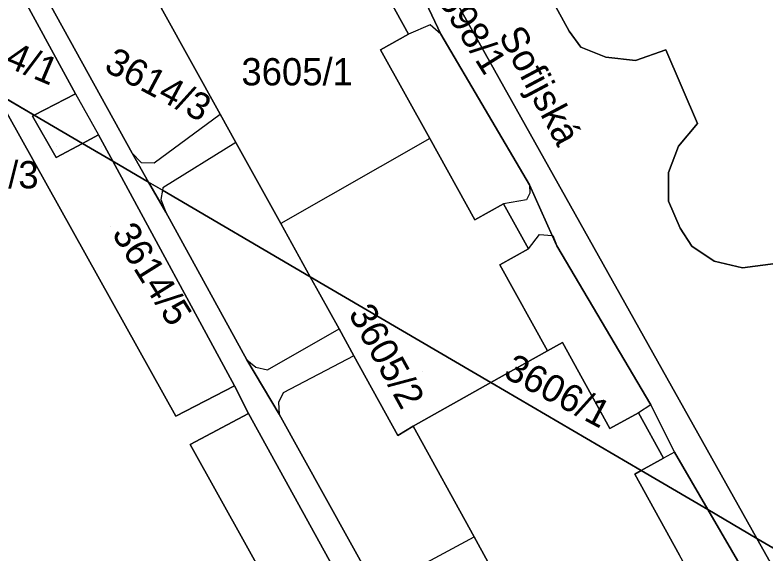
# Model space of a CAD drawing. Extents: x -262715 to -259381, y -1237238 to -1231182.
# Drawn here: x -261657.7 to -261602.6, y -1236025.5 to -1235986 of the extents above; entities that cross this region are included whole.
import ezdxf

# ---------------------------------------------------------------- set-up
doc = ezdxf.new("R2010")
doc.units = 0
for name, color, linetype in [('body_kn', 7, 'Continuous'), ('kladpar_druhypozemkov', 7, 'Continuous'), ('kladpar_hranice', 7, 'Continuous'), ('kladpar_parcelnecisla', 7, 'Continuous'), ('kladpar_plochy', 7, 'Continuous'), ('kladpar_sipky', 7, 'Continuous'), ('popisy', 7, 'Continuous'), ('zappar_hrandruhpozemk', 7, 'Continuous')]:
    doc.layers.add(name, color=color, linetype=linetype)

msp = doc.modelspace()

# ---------------------------------------------------------------- linework, layer by layer
at = {"layer": 'body_kn'}
for p, q in [((-261627.23, -1235986.66), (-261627.23, -1235986.66)), ((-261628.81, -1235987.35), (-261628.81, -1235987.35)), ((-261626.44, -1235987.35), (-261626.44, -1235987.35)), ((-261626.44, -1235987.35), (-261626.44, -1235987.35)), ((-261617.04, -1235987.14), (-261617.04, -1235987.14)), ((-261616.18, -1235988.31), (-261616.18, -1235988.31)), ((-261630.88, -1235988.5), (-261630.88, -1235988.5)), ((-261609.93, -1235988.5), (-261609.93, -1235988.5)), ((-261614.35, -1235989.05), (-261614.35, -1235989.05)), ((-261612.17, -1235989.28), (-261612.17, -1235989.28)), ((-261653.25, -1235991.72), (-261653.25, -1235991.72)), ((-261653.25, -1235991.72), (-261653.25, -1235991.72)), ((-261656.41, -1235993.37), (-261656.41, -1235993.37)), ((-261656.41, -1235993.37), (-261656.41, -1235993.37)), ((-261656.28, -1235993.3), (-261656.28, -1235993.3)), ((-261642.65, -1235993.21), (-261642.65, -1235993.21)), ((-261607.62, -1235993.9), (-261607.62, -1235993.9)), ((-261651.57, -1235994.73), (-261651.57, -1235994.73)), ((-261627.26, -1235995.01), (-261627.26, -1235995.01)), ((-261627.26, -1235995.01), (-261627.26, -1235995.01)), ((-261652.75, -1235995.36), (-261652.75, -1235995.36)), ((-261652.75, -1235995.36), (-261652.75, -1235995.36)), ((-261641.49, -1235995.3), (-261641.49, -1235995.3)), ((-261641.49, -1235995.3), (-261641.49, -1235995.3)), ((-261609.01, -1235995.56), (-261609.01, -1235995.56)), ((-261649.11, -1235996.09), (-261649.11, -1235996.09)), ((-261649.11, -1235996.09), (-261649.11, -1235996.09)), ((-261654.68, -1235996.39), (-261654.68, -1235996.39)), ((-261650.52, -1235996.67), (-261650.52, -1235996.67)), ((-261650.52, -1235996.67), (-261650.52, -1235996.67)), ((-261648.45, -1235996.76), (-261648.45, -1235996.76)), ((-261647.49, -1235996.79), (-261647.49, -1235996.79)), ((-261609.73, -1235997.49), (-261609.73, -1235997.49)), ((-261647.9, -1235998.2), (-261647.9, -1235998.2)), ((-261647.9, -1235998.2), (-261647.9, -1235998.2)), ((-261646.88, -1235998.8), (-261646.88, -1235998.8)), ((-261646.85, -1235998.61), (-261646.85, -1235998.61)), ((-261619.93, -1235998.41), (-261619.93, -1235998.41)), ((-261619.93, -1235998.41), (-261619.93, -1235998.41)), ((-261646.99, -1235999.48), (-261646.99, -1235999.48)), ((-261620.17, -1235999.49), (-261620.17, -1235999.49)), ((-261619.91, -1235999.02), (-261619.91, -1235999.02)), ((-261621.85, -1235999.8), (-261621.85, -1235999.8)), ((-261609.73, -1235999.59), (-261609.73, -1235999.59)), ((-261646.63, -1236000.41), (-261646.63, -1236000.41)), ((-261623.95, -1236000.97), (-261623.95, -1236000.97)), ((-261638.2, -1236001.24), (-261638.2, -1236001.24)), ((-261608.89, -1236001.57), (-261608.89, -1236001.57)), ((-261619.2, -1236002.04), (-261619.2, -1236002.04)), ((-261618.27, -1236002.12), (-261618.27, -1236002.12)), ((-261618.27, -1236002.12), (-261618.27, -1236002.12)), ((-261618.24, -1236002.12), (-261618.24, -1236002.12)), ((-261620.02, -1236003.09), (-261620.02, -1236003.09)), ((-261620.02, -1236003.09), (-261620.02, -1236003.09)), ((-261617.93, -1236002.88), (-261617.93, -1236002.88)), ((-261608.04, -1236002.91), (-261608.04, -1236002.91)), ((-261622.12, -1236004.26), (-261622.12, -1236004.26)), ((-261606.38, -1236003.99), (-261606.38, -1236003.99)), ((-261604.3, -1236004.48), (-261604.3, -1236004.48)), ((-261636.04, -1236005.14), (-261636.04, -1236005.14)), ((-261636.04, -1236005.14), (-261636.04, -1236005.14)), ((-261633.92, -1236008.96), (-261633.92, -1236008.96)), ((-261617.53, -1236009.97), (-261617.53, -1236009.97)), ((-261632.84, -1236010.93), (-261632.84, -1236010.93)), ((-261632.84, -1236010.93), (-261632.84, -1236010.93)), ((-261618.61, -1236010.57), (-261618.61, -1236010.57)), ((-261640.68, -1236011.22), (-261640.68, -1236011.22)), ((-261640.68, -1236011.22), (-261640.68, -1236011.22)), ((-261640.02, -1236011.77), (-261640.02, -1236011.77)), ((-261639.16, -1236011.97), (-261639.16, -1236011.97)), ((-261641.6, -1236013.13), (-261641.6, -1236013.13)), ((-261622.77, -1236012.9), (-261622.77, -1236012.9)), ((-261622.77, -1236012.9), (-261622.77, -1236012.9)), ((-261638.01, -1236013.65), (-261638.01, -1236013.65)), ((-261638.35, -1236014.35), (-261638.35, -1236014.35)), ((-261611.03, -1236014.53), (-261611.03, -1236014.53)), ((-261611.03, -1236014.53), (-261611.03, -1236014.53)), ((-261645.89, -1236015.37), (-261645.89, -1236015.37)), ((-261640.57, -1236015.16), (-261640.57, -1236015.16)), ((-261640.57, -1236015.16), (-261640.57, -1236015.16)), ((-261638.32, -1236015.22), (-261638.32, -1236015.22)), ((-261611.94, -1236015.11), (-261611.94, -1236015.11)), ((-261628.48, -1236016.1), (-261628.48, -1236016.1)), ((-261614.05, -1236016.27), (-261614.05, -1236016.27)), ((-261629.6, -1236016.78), (-261629.6, -1236016.78)), ((-261644.84, -1236017.45), (-261644.84, -1236017.45)), ((-261609.31, -1236017.99), (-261609.31, -1236017.99)), ((-261609.31, -1236017.99), (-261609.31, -1236017.99)), ((-261610.1, -1236018.45), (-261610.1, -1236018.45)), ((-261612.21, -1236019.61), (-261612.21, -1236019.61)), ((-261612.21, -1236019.61), (-261612.21, -1236019.61)), ((-261611.74, -1236019.35), (-261611.74, -1236019.35)), ((-261606.85, -1236022.21), (-261606.85, -1236022.21)), ((-261606.85, -1236022.21), (-261606.85, -1236022.21)), ((-261624, -1236024.2), (-261624, -1236024.2)), ((-261603.25, -1236024.32), (-261603.25, -1236024.32)), ((-261603.25, -1236024.32), (-261603.25, -1236024.32))]:
    msp.add_line(p, q, dxfattribs=at)
at = {"layer": 'kladpar_druhypozemkov'}
for p, q in [((-261637.15, -1235989.27), (-261637.15, -1235989.27)), ((-261654.2, -1235996.18), (-261654.2, -1235996.18)), ((-261651.69, -1235996.09), (-261651.69, -1235996.09)), ((-261650.66, -1236001.48), (-261650.66, -1236001.48)), ((-261627.8, -1236012.12), (-261627.8, -1236012.12)), ((-261617.86, -1236012.24), (-261617.86, -1236012.24))]:
    msp.add_line(p, q, dxfattribs=at)
at = {"layer": 'kladpar_hranice'}
for p, q in [((-261659.15, -1235991.62), (-261656.28, -1235993.3)), ((-261656.28, -1235993.3), (-261659.15, -1235991.62)), ((-261656.41, -1235993.37), (-261656.28, -1235993.3)), ((-261656.28, -1235993.3), (-261652.75, -1235995.36)), ((-261652.75, -1235995.36), (-261656.28, -1235993.3)), ((-261650.52, -1235996.67), (-261652.75, -1235995.36)), ((-261652.75, -1235995.36), (-261650.52, -1235996.67)), ((-261650.52, -1235996.67), (-261647.9, -1235998.2)), ((-261647.9, -1235998.2), (-261650.52, -1235996.67)), ((-261636.04, -1236005.14), (-261622.77, -1236012.9)), ((-261622.77, -1236012.9), (-261636.04, -1236005.14)), ((-261622.77, -1236012.9), (-261611.74, -1236019.35)), ((-261611.74, -1236019.35), (-261622.77, -1236012.9)), ((-261612.21, -1236019.61), (-261611.74, -1236019.35)), ((-261611.74, -1236019.35), (-261606.85, -1236022.21)), ((-261606.85, -1236022.21), (-261611.74, -1236019.35)), ((-261606.85, -1236022.21), (-261603.25, -1236024.32)), ((-261603.25, -1236024.32), (-261606.85, -1236022.21)), ((-261603.25, -1236024.32), (-261592.06, -1236030.86)), ((-261592.06, -1236030.86), (-261603.25, -1236024.32))]:
    msp.add_line(p, q, dxfattribs=at)
for points in [[(-261700.14, -1235910.44), (-261695.81, -1235907.56), (-261696.3, -1235908.79), (-261696.13, -1235910.23), (-261682.96, -1235934.42), (-261680.87, -1235938.67), (-261674.47, -1235950.17), (-261672.63, -1235953.64), (-261666.32, -1235964.83), (-261664.28, -1235968.72), (-261657.45, -1235980.76), (-261655.55, -1235984.37), (-261649.11, -1235996.09), (-261647.9, -1235998.2)], [(-261647.9, -1235998.2), (-261649.11, -1235996.09), (-261655.55, -1235984.37), (-261657.45, -1235980.76), (-261664.28, -1235968.72), (-261666.32, -1235964.83), (-261672.63, -1235953.64), (-261674.47, -1235950.17), (-261680.87, -1235938.67), (-261682.96, -1235934.42), (-261696.13, -1235910.23), (-261696.3, -1235908.79), (-261695.81, -1235907.56)], [(-261666.06, -1235910.46), (-261663.16, -1235908.74), (-261656.54, -1235920.4), (-261655.84, -1235920.95), (-261655.07, -1235920.8), (-261652.4, -1235919.49), (-261647.19, -1235916.68), (-261635.61, -1235910.73), (-261633.5, -1235909.46), (-261632.4, -1235911.14), (-261634.48, -1235912.49), (-261643.77, -1235917.41), (-261646.59, -1235919.26), (-261649.17, -1235921.91), (-261651.23, -1235925), (-261652.33, -1235928.69), (-261653.06, -1235932.55), (-261652.34, -1235936.44), (-261650.33, -1235940.2), (-261644.15, -1235951.36), (-261603.25, -1236024.32)], [(-261656.28, -1235993.3), (-261653.25, -1235991.72), (-261657.83, -1235983.33), (-261658.65, -1235981.75), (-261674.3, -1235953.82), (-261675.47, -1235951.64), (-261694.09, -1235918.19), (-261695.04, -1235916.46), (-261697.94, -1235911.57), (-261698.79, -1235910.77), (-261700.14, -1235910.44)], [(-261606.85, -1236022.21), (-261609.31, -1236017.99), (-261611.03, -1236014.53), (-261617.93, -1236002.88), (-261618.27, -1236002.12), (-261619.93, -1235998.41), (-261626.44, -1235987.35), (-261628.45, -1235983.11), (-261634.94, -1235971.68), (-261637.19, -1235967.84), (-261644.32, -1235955.72), (-261646.13, -1235952.42), (-261652.77, -1235940.57), (-261654.43, -1235937.15), (-261654.92, -1235933.95), (-261654.76, -1235930.83), (-261658.51, -1235924.39), (-261661.36, -1235919.14), (-261665.19, -1235912.1), (-261666.06, -1235910.46)], [(-261670.44, -1235915.11), (-261665.19, -1235912.1), (-261661.36, -1235919.14), (-261658.51, -1235924.39), (-261654.76, -1235930.83), (-261654.92, -1235933.95), (-261654.43, -1235937.15), (-261652.77, -1235940.57), (-261646.13, -1235952.42), (-261644.32, -1235955.72), (-261637.19, -1235967.84), (-261634.94, -1235971.68), (-261628.45, -1235983.11), (-261626.44, -1235987.35), (-261619.93, -1235998.41), (-261618.27, -1236002.12), (-261617.93, -1236002.88), (-261611.03, -1236014.53), (-261609.31, -1236017.99), (-261606.85, -1236022.21)], [(-261603.25, -1236024.32), (-261644.15, -1235951.36)], [(-261611.74, -1236019.35), (-261610.1, -1236018.45), (-261611.94, -1236015.11), (-261614.05, -1236016.27), (-261617.53, -1236009.97), (-261618.61, -1236010.57), (-261622.12, -1236004.26), (-261620.02, -1236003.09), (-261621.85, -1235999.8), (-261623.95, -1236000.97), (-261627.26, -1235995.01), (-261630.88, -1235988.5), (-261628.81, -1235987.35), (-261630.64, -1235984.05), (-261632.71, -1235985.2), (-261636.01, -1235979.27), (-261639.31, -1235973.34), (-261637.25, -1235972.19), (-261639.06, -1235968.88), (-261641.14, -1235970.04), (-261644.3, -1235964.36), (-261648.09, -1235957.54)], [(-261659.69, -1235962.41), (-261658.56, -1235964.46), (-261655.2, -1235970.53), (-261651.03, -1235978.06), (-261649.9, -1235980.11), (-261646.84, -1235985.64), (-261642.65, -1235993.21), (-261641.49, -1235995.3), (-261638.2, -1236001.24), (-261636.04, -1236005.14)], [(-261655.2, -1235970.53), (-261644.3, -1235964.36), (-261641.14, -1235970.04), (-261639.06, -1235968.88), (-261637.25, -1235972.19), (-261639.31, -1235973.34), (-261636.01, -1235979.27), (-261632.71, -1235985.2), (-261630.64, -1235984.05), (-261628.81, -1235987.35), (-261630.88, -1235988.5), (-261627.26, -1235995.01), (-261623.95, -1236000.97), (-261621.85, -1235999.8), (-261620.02, -1236003.09), (-261622.12, -1236004.26), (-261618.61, -1236010.57), (-261622.77, -1236012.9)], [(-261636.04, -1236005.14), (-261638.2, -1236001.24), (-261641.49, -1235995.3), (-261642.65, -1235993.21), (-261646.84, -1235985.64), (-261649.9, -1235980.11), (-261651.03, -1235978.06), (-261655.2, -1235970.53)], [(-261665.76, -1235987.75), (-261657.83, -1235983.33), (-261653.25, -1235991.72), (-261656.28, -1235993.3)], [(-261601.9, -1236004.16), (-261604.3, -1236004.48), (-261606.38, -1236003.99), (-261608.04, -1236002.91), (-261608.89, -1236001.57), (-261609.73, -1235999.59), (-261609.73, -1235997.49), (-261609.01, -1235995.56), (-261607.62, -1235993.9), (-261609.93, -1235988.5), (-261612.17, -1235989.28), (-261614.35, -1235989.05), (-261616.18, -1235988.31), (-261617.04, -1235987.14), (-261618.27, -1235984.83)], [(-261618.27, -1235984.83), (-261617.04, -1235987.14), (-261616.18, -1235988.31), (-261614.35, -1235989.05), (-261612.17, -1235989.28), (-261609.93, -1235988.5), (-261607.62, -1235993.9), (-261609.01, -1235995.56), (-261609.73, -1235997.49), (-261609.73, -1235999.59), (-261608.89, -1236001.57), (-261608.04, -1236002.91), (-261606.38, -1236003.99), (-261604.3, -1236004.48), (-261601.9, -1236004.16)], [(-261659.37, -1235991.22), (-261659.15, -1235991.62), (-261645.89, -1236015.37), (-261641.6, -1236013.13), (-261640.57, -1236015.16), (-261644.84, -1236017.45), (-261620.32, -1236061.49), (-261612.68, -1236065.74), (-261611.06, -1236068.53), (-261622.18, -1236062.34), (-261637.19, -1236068.77), (-261660.5, -1236026.2), (-261662.24, -1236030.9), (-261668.09, -1236046.76), (-261669.85, -1236046.53), (-261663.82, -1236030.1), (-261661.6, -1236024.18), (-261675.14, -1235999.74), (-261672.65, -1235998.38), (-261670.9, -1235997.38), (-261659.61, -1235991.35), (-261659.37, -1235991.22)], [(-261650.52, -1235996.67), (-261641.6, -1236013.13), (-261645.89, -1236015.37), (-261659.15, -1235991.62)], [(-261656.28, -1235993.3), (-261656.41, -1235993.37), (-261654.68, -1235996.39), (-261652.75, -1235995.36)], [(-261652.75, -1235995.36), (-261654.68, -1235996.39), (-261656.41, -1235993.37)], [(-261650.52, -1235996.67), (-261651.57, -1235994.73), (-261652.75, -1235995.36)], [(-261652.75, -1235995.36), (-261651.57, -1235994.73), (-261650.52, -1235996.67)], [(-261660.79, -1236082.28), (-261657.56, -1236081.47), (-261658.74, -1236077.09), (-261650.64, -1236074.94), (-261649.43, -1236079.35), (-261611.8, -1236069.42), (-261611.21, -1236069.04), (-261611.06, -1236068.53), (-261612.68, -1236065.74), (-261640.57, -1236015.16), (-261641.6, -1236013.13), (-261650.52, -1235996.67)], [(-261647.9, -1235998.2), (-261646.63, -1236000.41), (-261640.68, -1236011.22), (-261638.32, -1236015.22), (-261631.49, -1236027.51), (-261629.83, -1236030.97), (-261623.18, -1236043.17), (-261621.56, -1236046.17), (-261615.02, -1236058.24), (-261613.26, -1236061.42), (-261610.77, -1236066.07), (-261610.24, -1236066.68), (-261609.28, -1236067), (-261603.31, -1236063.61), (-261601.54, -1236066.77), (-261603.15, -1236067.76), (-261610.52, -1236070.92), (-261613.9, -1236071.86), (-261627.87, -1236075.74), (-261631.24, -1236076.67), (-261638.47, -1236078.68), (-261641.36, -1236079.48), (-261655.33, -1236083.36), (-261660.25, -1236084.77)], [(-261647.9, -1235998.2), (-261646.88, -1235998.8), (-261636.04, -1236005.14)], [(-261631.49, -1236027.51), (-261638.32, -1236015.22), (-261640.68, -1236011.22), (-261646.63, -1236000.41), (-261647.9, -1235998.2)], [(-261636.04, -1236005.14), (-261646.88, -1235998.8), (-261647.9, -1235998.2)], [(-261622.77, -1236012.9), (-261628.48, -1236016.1), (-261629.6, -1236016.78), (-261632.84, -1236010.93), (-261633.92, -1236008.96), (-261636.04, -1236005.14)], [(-261636.04, -1236005.14), (-261633.92, -1236008.96), (-261632.84, -1236010.93), (-261629.6, -1236016.78), (-261628.48, -1236016.1), (-261624, -1236024.2), (-261622.99, -1236026.04)], [(-261622.77, -1236012.9), (-261618.61, -1236010.57), (-261617.53, -1236009.97), (-261614.05, -1236016.27), (-261611.94, -1236015.11), (-261610.1, -1236018.45), (-261611.74, -1236019.35)], [(-261622.99, -1236026.04), (-261624, -1236024.2), (-261628.48, -1236016.1), (-261622.77, -1236012.9)], [(-261640.57, -1236015.16), (-261612.68, -1236065.74), (-261620.32, -1236061.49), (-261644.84, -1236017.45), (-261640.57, -1236015.16)], [(-261611.74, -1236019.35), (-261612.21, -1236019.61), (-261608.94, -1236025.55)], [(-261606.85, -1236022.21), (-261602.43, -1236029.8), (-261600.62, -1236033.25), (-261593.86, -1236044.88), (-261592.45, -1236048.18), (-261588.83, -1236053.92), (-261589.22, -1236055.63), (-261593.15, -1236057.85), (-261593.48, -1236057.24), (-261591.96, -1236056.36), (-261595.39, -1236050.12), (-261593.28, -1236048.96), (-261595.12, -1236045.63), (-261597.23, -1236046.8), (-261600.53, -1236040.81), (-261603.79, -1236034.88), (-261601.67, -1236033.71), (-261603.51, -1236030.36), (-261605.64, -1236031.53), (-261608.94, -1236025.55), (-261612.21, -1236019.61)], [(-261612.79, -1236100.28), (-261600.77, -1236093.1), (-261598.62, -1236091.82), (-261581.08, -1236081.34), (-261578.13, -1236078.81), (-261577.1, -1236077.69), (-261577.04, -1236076.26), (-261577.61, -1236074.48), (-261583.21, -1236064.29), (-261585.35, -1236060.49), (-261585.91, -1236059.3), (-261587.45, -1236058.64), (-261591.51, -1236060.91), (-261593.15, -1236057.85), (-261589.22, -1236055.63), (-261588.83, -1236053.92), (-261592.45, -1236048.18), (-261593.86, -1236044.88), (-261600.62, -1236033.25), (-261602.43, -1236029.8), (-261606.85, -1236022.21)], [(-261643.83, -1236131.3), (-261651.87, -1236117.13), (-261650.02, -1236118.71), (-261648.18, -1236119.58), (-261646.19, -1236119.98), (-261644.26, -1236119.99), (-261641.93, -1236119.39), (-261639.77, -1236118.33), (-261614.29, -1236103.16), (-261580.3, -1236082.93), (-261576.34, -1236080.15), (-261575.28, -1236078.84), (-261574.98, -1236076.27), (-261575.25, -1236075.04), (-261576.45, -1236072.28), (-261600.64, -1236028.98), (-261603.25, -1236024.32)], [(-261603.25, -1236024.32), (-261600.64, -1236028.98), (-261576.45, -1236072.28), (-261575.25, -1236075.04), (-261574.98, -1236076.27), (-261575.28, -1236078.84), (-261576.34, -1236080.15), (-261580.3, -1236082.93), (-261614.29, -1236103.16)]]:
    msp.add_lwpolyline(points, dxfattribs=at)
at = {"layer": 'kladpar_plochy'}
for points in [[(-261644.15, -1235951.36), (-261603.25, -1236024.32), (-261606.85, -1236022.21), (-261609.31, -1236017.99), (-261611.03, -1236014.53), (-261617.93, -1236002.88), (-261618.27, -1236002.12), (-261619.93, -1235998.41), (-261626.44, -1235987.35), (-261628.45, -1235983.11), (-261634.94, -1235971.68), (-261637.19, -1235967.84), (-261644.32, -1235955.72)], [(-261592.06, -1236030.86), (-261603.25, -1236024.32), (-261644.15, -1235951.36)], [(-261672.63, -1235953.64), (-261666.32, -1235964.83), (-261664.28, -1235968.72), (-261657.45, -1235980.76), (-261655.55, -1235984.37), (-261649.11, -1235996.09), (-261647.9, -1235998.2), (-261650.52, -1235996.67), (-261651.57, -1235994.73), (-261652.75, -1235995.36), (-261656.28, -1235993.3), (-261653.25, -1235991.72), (-261657.83, -1235983.33), (-261658.65, -1235981.75), (-261674.3, -1235953.82)], [(-261659.69, -1235962.41), (-261658.56, -1235964.46), (-261655.2, -1235970.53), (-261651.03, -1235978.06), (-261649.9, -1235980.11), (-261646.84, -1235985.64), (-261642.65, -1235993.21), (-261641.49, -1235995.3), (-261638.2, -1236001.24), (-261636.04, -1236005.14), (-261646.88, -1235998.8), (-261647.9, -1235998.2), (-261649.11, -1235996.09), (-261655.55, -1235984.37), (-261657.45, -1235980.76), (-261664.28, -1235968.72), (-261666.32, -1235964.83), (-261672.63, -1235953.64)], [(-261628.45, -1235983.11), (-261626.44, -1235987.35), (-261619.93, -1235998.41), (-261618.27, -1236002.12), (-261617.93, -1236002.88), (-261611.03, -1236014.53), (-261609.31, -1236017.99), (-261606.85, -1236022.21), (-261611.74, -1236019.35), (-261610.1, -1236018.45), (-261611.94, -1236015.11), (-261614.05, -1236016.27), (-261617.53, -1236009.97), (-261618.61, -1236010.57), (-261622.12, -1236004.26), (-261620.02, -1236003.09), (-261621.85, -1235999.8), (-261623.95, -1236000.97), (-261627.26, -1235995.01), (-261630.88, -1235988.5), (-261628.81, -1235987.35), (-261630.64, -1235984.05)], [(-261630.64, -1235984.05), (-261628.81, -1235987.35), (-261630.88, -1235988.5), (-261627.26, -1235995.01), (-261623.95, -1236000.97), (-261621.85, -1235999.8), (-261620.02, -1236003.09), (-261622.12, -1236004.26), (-261618.61, -1236010.57), (-261622.77, -1236012.9), (-261636.04, -1236005.14), (-261638.2, -1236001.24), (-261641.49, -1235995.3), (-261642.65, -1235993.21), (-261646.84, -1235985.64)], [(-261601.9, -1236004.16), (-261604.3, -1236004.48), (-261606.38, -1236003.99), (-261608.04, -1236002.91), (-261608.89, -1236001.57), (-261609.73, -1235999.59), (-261609.73, -1235997.49), (-261609.01, -1235995.56), (-261607.62, -1235993.9), (-261609.93, -1235988.5), (-261612.17, -1235989.28), (-261614.35, -1235989.05), (-261616.18, -1235988.31), (-261617.04, -1235987.14), (-261618.27, -1235984.83)], [(-261618.27, -1235984.83), (-261617.04, -1235987.14), (-261616.18, -1235988.31), (-261614.35, -1235989.05), (-261612.17, -1235989.28), (-261609.93, -1235988.5), (-261607.62, -1235993.9), (-261609.01, -1235995.56), (-261609.73, -1235997.49), (-261609.73, -1235999.59), (-261608.89, -1236001.57), (-261608.04, -1236002.91), (-261606.38, -1236003.99), (-261604.3, -1236004.48), (-261601.9, -1236004.16)], [(-261612.68, -1236065.74), (-261640.57, -1236015.16), (-261641.6, -1236013.13), (-261650.52, -1235996.67), (-261647.9, -1235998.2), (-261646.63, -1236000.41), (-261640.68, -1236011.22), (-261638.32, -1236015.22), (-261631.49, -1236027.51)], [(-261631.49, -1236027.51), (-261638.32, -1236015.22), (-261640.68, -1236011.22), (-261646.63, -1236000.41), (-261647.9, -1235998.2), (-261646.88, -1235998.8), (-261636.04, -1236005.14), (-261633.92, -1236008.96), (-261632.84, -1236010.93), (-261629.6, -1236016.78), (-261628.48, -1236016.1), (-261624, -1236024.2), (-261622.99, -1236026.04)], [(-261622.99, -1236026.04), (-261624, -1236024.2), (-261628.48, -1236016.1), (-261622.77, -1236012.9), (-261611.74, -1236019.35), (-261612.21, -1236019.61), (-261608.94, -1236025.55)], [(-261602.43, -1236029.8), (-261606.85, -1236022.21), (-261603.25, -1236024.32), (-261600.64, -1236028.98)], [(-261600.64, -1236028.98), (-261603.25, -1236024.32), (-261592.06, -1236030.86)]]:
    msp.add_lwpolyline(points, dxfattribs=at)
for points in [[(-261665.76, -1235987.75), (-261657.83, -1235983.33), (-261653.25, -1235991.72), (-261656.28, -1235993.3), (-261659.15, -1235991.62), (-261659.37, -1235991.22), (-261659.61, -1235991.35)], [(-261659.37, -1235991.22), (-261659.15, -1235991.62), (-261645.89, -1236015.37), (-261641.6, -1236013.13), (-261640.57, -1236015.16), (-261644.84, -1236017.45), (-261620.32, -1236061.49), (-261612.68, -1236065.74), (-261611.06, -1236068.53), (-261622.18, -1236062.34), (-261637.19, -1236068.77), (-261660.5, -1236026.2), (-261662.24, -1236030.9), (-261668.09, -1236046.76), (-261669.85, -1236046.53), (-261663.82, -1236030.1), (-261661.6, -1236024.18), (-261675.14, -1235999.74), (-261672.65, -1235998.38), (-261670.9, -1235997.38), (-261659.61, -1235991.35)], [(-261659.15, -1235991.62), (-261656.28, -1235993.3), (-261656.41, -1235993.37), (-261654.68, -1235996.39), (-261652.75, -1235995.36), (-261650.52, -1235996.67), (-261641.6, -1236013.13), (-261645.89, -1236015.37)], [(-261656.41, -1235993.37), (-261656.28, -1235993.3), (-261652.75, -1235995.36), (-261654.68, -1235996.39)], [(-261652.75, -1235995.36), (-261651.57, -1235994.73), (-261650.52, -1235996.67)], [(-261636.04, -1236005.14), (-261622.77, -1236012.9), (-261628.48, -1236016.1), (-261629.6, -1236016.78), (-261632.84, -1236010.93), (-261633.92, -1236008.96)], [(-261622.77, -1236012.9), (-261618.61, -1236010.57), (-261617.53, -1236009.97), (-261614.05, -1236016.27), (-261611.94, -1236015.11), (-261610.1, -1236018.45), (-261611.74, -1236019.35)], [(-261640.57, -1236015.16), (-261612.68, -1236065.74), (-261620.32, -1236061.49), (-261644.84, -1236017.45)], [(-261612.21, -1236019.61), (-261611.74, -1236019.35), (-261606.85, -1236022.21), (-261602.43, -1236029.8), (-261600.62, -1236033.25), (-261593.86, -1236044.88), (-261592.45, -1236048.18), (-261588.83, -1236053.92), (-261589.22, -1236055.63), (-261593.15, -1236057.85), (-261593.48, -1236057.24), (-261591.96, -1236056.36), (-261595.39, -1236050.12), (-261593.28, -1236048.96), (-261595.12, -1236045.63), (-261597.23, -1236046.8), (-261600.53, -1236040.81), (-261603.79, -1236034.88), (-261601.67, -1236033.71), (-261603.51, -1236030.36), (-261605.64, -1236031.53), (-261608.94, -1236025.55)]]:
    msp.add_lwpolyline(points, close=True, dxfattribs=at)
at = {"layer": 'kladpar_sipky'}
for p, q in [((-261654.67, -1235995.59), (-261654.67, -1235995.59)), ((-261651.38, -1235995.59), (-261651.38, -1235995.59))]:
    msp.add_line(p, q, dxfattribs=at)
at = {"layer": 'zappar_hrandruhpozemk'}
for p, q in [((-261627.23, -1235986.66), (-261628.81, -1235987.35)), ((-261626.44, -1235987.35), (-261627.23, -1235986.66)), ((-261653.25, -1235991.72), (-261651.57, -1235994.73)), ((-261647.49, -1235996.79), (-261642.65, -1235993.21)), ((-261627.26, -1235995.01), (-261638.2, -1236001.24)), ((-261641.49, -1235995.3), (-261646.85, -1235998.61)), ((-261620.17, -1235999.49), (-261621.85, -1235999.8)), ((-261620.02, -1236003.09), (-261619.2, -1236002.04)), ((-261619.2, -1236002.04), (-261618.27, -1236002.12)), ((-261639.16, -1236011.97), (-261633.92, -1236008.96)), ((-261632.84, -1236010.93), (-261638.01, -1236013.65)), ((-261611.03, -1236014.53), (-261611.94, -1236015.11)), ((-261609.31, -1236017.99), (-261610.1, -1236018.45)), ((-261630.8, -1236027.86), (-261624, -1236024.2))]:
    msp.add_line(p, q, dxfattribs=at)
for points in [[(-261649.11, -1235996.09), (-261648.45, -1235996.76), (-261647.49, -1235996.79)], [(-261646.85, -1235998.61), (-261646.88, -1235998.8), (-261646.99, -1235999.48), (-261646.63, -1236000.41)], [(-261619.93, -1235998.41), (-261619.91, -1235999.02), (-261620.17, -1235999.49)], [(-261618.27, -1236002.12), (-261618.24, -1236002.12), (-261617.93, -1236002.88)], [(-261640.68, -1236011.22), (-261640.02, -1236011.77), (-261639.16, -1236011.97)], [(-261638.01, -1236013.65), (-261638.35, -1236014.35), (-261638.32, -1236015.22)]]:
    msp.add_lwpolyline(points, dxfattribs=at)

# ---------------------------------------------------------------- texts
at = {"layer": 'kladpar_parcelnecisla'}
for s, rotation, p in [('3598/1', 302, (-261627.541, -1235983.534)), ('3614/1', 337, (-261662.616, -1235987.945)), ('3614/3', 332, (-261651.251, -1235989.992)), ('3614/5', 302, (-261650.635, -1236001.981)), ('3605/2', 299, (-261633.27, -1236007.842)), ('3606/1', 332, (-261621.948, -1236012.455))]:
    msp.add_text(s, height=2, rotation=rotation, dxfattribs=at).set_placement(p)
for s, p in [('3605/1', (-261641.08, -1235991.11)), ('3611/3', (-261664.146, -1235998.66))]:
    msp.add_text(s, height=2, dxfattribs=at).set_placement(p)
at = {"layer": 'popisy'}
msp.add_text('Sofijská', height=2, rotation=298, dxfattribs=at).set_placement((-261622.247, -1235987.434))

doc.saveas('drawing.dxf')
